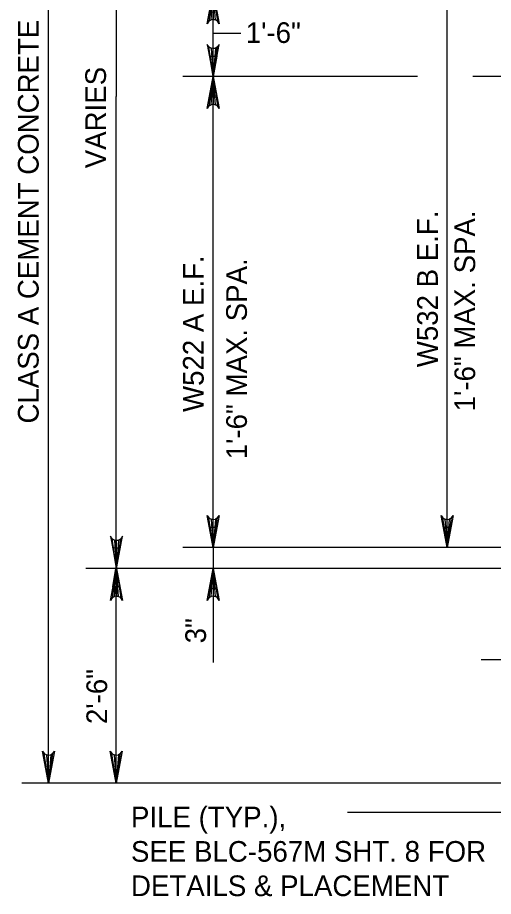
# Model space of a CAD drawing. Extents: x 638340 to 640242, y 295465 to 298435.
# Drawn here: x 639000.8 to 639069.8, y 295804.4 to 295932 of the extents above; entities that cross this region are included whole.
import ezdxf

# ---------------------------------------------------------------- set-up
doc = ezdxf.new("R2010")
doc.units = 0
doc.layers.add('Level 3', color=7, linetype='Continuous')
doc.layers.add('Level 4', color=7, linetype='Continuous')

msp = doc.modelspace()

# ---------------------------------------------------------------- linework, layer by layer
at = {"layer": 'Level 3'}
for p, q in [((639029.13, 295929.71), (639033.15, 295929.71)), ((639105.85, 295816.54), (639048.6, 295816.54))]:
    msp.add_line(p, q, dxfattribs=at)
at = {"layer": 'Level 4'}
for p, q in [((639005.25, 295820.81), (639005.25, 295989.02)), ((639015.06, 295989.02), (639015.06, 295920.5)), ((639063.04, 295855.02), (639063.04, 295937.09)), ((639029.13, 295926.36), (639029.13, 295932.78)), ((639028.55, 295923.41), (639024.71, 295923.41)), ((639058.77, 295923.41), (639024.71, 295923.41)), ((639029.13, 295855.02), (639029.13, 295923.41)), ((639124.35, 295923.41), (639066.79, 295923.41)), ((639015.06, 295854.94), (639015.06, 295920.5)), ((639085.93, 295855.02), (639024.71, 295855.02)), ((639029.13, 295855.02), (639029.13, 295838.31)), ((639083.79, 295855.02), (639053.64, 295855.02)), ((639094.01, 295851.99), (639010.64, 295851.99)), ((639094.01, 295851.99), (639024.01, 295851.99)), ((639060.4, 295851.99), (639024.71, 295851.99)), ((639015.06, 295820.81), (639015.06, 295849.31)), ((639029.13, 295849.04), (639029.13, 295846.1)), ((639097.46, 295838.69), (639067.96, 295838.69)), ((639094.01, 295820.81), (639001.39, 295820.81))]:
    msp.add_line(p, q, dxfattribs=at)
for points in [[(639029.13, 295935.72), (639030, 295931.07), (639029.76, 295931.43), (639029.45, 295931.62), (639029.13, 295931.67), (639028.82, 295931.62), (639028.51, 295931.43), (639028.26, 295931.07), (639029.13, 295935.72), (639028.51, 295931.43), (639028.82, 295931.62), (639029.13, 295935.72), (639029.13, 295931.67), (639029.45, 295931.62), (639029.13, 295935.72), (639029.76, 295931.43)], [(639029.13, 295923.41), (639030, 295928.06), (639029.76, 295927.71), (639029.45, 295927.52), (639029.13, 295927.47), (639028.82, 295927.52), (639028.51, 295927.71), (639028.26, 295928.06), (639029.13, 295923.41), (639028.51, 295927.71), (639028.82, 295927.52), (639029.13, 295923.41), (639029.13, 295927.47), (639029.45, 295927.52), (639029.13, 295923.41), (639029.76, 295927.71)], [(639029.13, 295923.41), (639030, 295918.76), (639029.76, 295919.12), (639029.45, 295919.3), (639029.13, 295919.36), (639028.82, 295919.3), (639028.51, 295919.12), (639028.26, 295918.76), (639029.13, 295923.41), (639028.51, 295919.12), (639028.82, 295919.3), (639029.13, 295923.41), (639029.13, 295919.36), (639029.45, 295919.3), (639029.13, 295923.41), (639029.76, 295919.12)], [(639029.13, 295855.02), (639028.26, 295859.67), (639028.51, 295859.31), (639028.82, 295859.13), (639029.13, 295859.07), (639029.45, 295859.13), (639029.76, 295859.31), (639030, 295859.67), (639029.13, 295855.02), (639029.76, 295859.31), (639029.45, 295859.13), (639029.13, 295855.02), (639029.13, 295859.07), (639028.82, 295859.13), (639029.13, 295855.02), (639028.51, 295859.31)], [(639063.04, 295855.02), (639062.16, 295859.67), (639062.41, 295859.31), (639062.72, 295859.13), (639063.04, 295859.07), (639063.35, 295859.13), (639063.66, 295859.31), (639063.91, 295859.67), (639063.04, 295855.02), (639063.66, 295859.31), (639063.35, 295859.13), (639063.04, 295855.02), (639063.04, 295859.07), (639062.72, 295859.13), (639063.04, 295855.02), (639062.41, 295859.31)], [(639015.1, 295851.99), (639015.97, 295856.64), (639015.72, 295856.28), (639015.41, 295856.1), (639015.1, 295856.04), (639014.79, 295856.1), (639014.48, 295856.28), (639014.23, 295856.64), (639015.1, 295851.99), (639014.48, 295856.28), (639014.79, 295856.1), (639015.1, 295851.99), (639015.1, 295856.04), (639015.41, 295856.1), (639015.1, 295851.99), (639015.72, 295856.28)], [(639015.1, 295851.99), (639015.97, 295847.34), (639015.72, 295847.7), (639015.41, 295847.88), (639015.1, 295847.94), (639014.79, 295847.88), (639014.48, 295847.7), (639014.23, 295847.34), (639015.1, 295851.99), (639014.48, 295847.7), (639014.79, 295847.88), (639015.1, 295851.99), (639015.1, 295847.94), (639015.41, 295847.88), (639015.1, 295851.99), (639015.72, 295847.7)], [(639029.13, 295851.99), (639030, 295847.34), (639029.76, 295847.7), (639029.45, 295847.88), (639029.13, 295847.94), (639028.82, 295847.88), (639028.51, 295847.7), (639028.26, 295847.34), (639029.13, 295851.99), (639028.51, 295847.7), (639028.82, 295847.88), (639029.13, 295851.99), (639029.13, 295847.94), (639029.45, 295847.88), (639029.13, 295851.99), (639029.76, 295847.7)], [(639005.25, 295820.81), (639004.38, 295825.46), (639004.63, 295825.11), (639004.94, 295824.92), (639005.25, 295824.87), (639005.56, 295824.92), (639005.88, 295825.11), (639006.12, 295825.46), (639005.25, 295820.81), (639005.88, 295825.11), (639005.56, 295824.92), (639005.25, 295820.81), (639005.25, 295824.87), (639004.94, 295824.92), (639005.25, 295820.81), (639004.63, 295825.11)], [(639015.06, 295820.81), (639014.18, 295825.46), (639014.43, 295825.11), (639014.74, 295824.92), (639015.06, 295824.87), (639015.37, 295824.92), (639015.68, 295825.11), (639015.93, 295825.46), (639015.06, 295820.81), (639015.68, 295825.11), (639015.37, 295824.92), (639015.06, 295820.81), (639015.06, 295824.87), (639014.74, 295824.92), (639015.06, 295820.81), (639014.43, 295825.11)]]:
    msp.add_lwpolyline(points, dxfattribs=at)
for points in [[(639028.64, 295926.36), (639029.63, 295926.36), (639029.13, 295923.41)], [(639028.64, 295920.47), (639029.63, 295920.47), (639029.13, 295923.41)], [(639028.64, 295857.96), (639029.63, 295857.96), (639029.13, 295855.02)], [(639062.54, 295857.96), (639063.53, 295857.96), (639063.04, 295855.02)], [(639015.55, 295854.94), (639014.57, 295854.94), (639015.06, 295851.99)], [(639015.55, 295849.31), (639014.57, 295849.31), (639015.06, 295852.25)], [(639028.64, 295849.04), (639029.63, 295849.04), (639029.13, 295851.99)]]:
    msp.add_lwpolyline(points, close=True, dxfattribs=at)

# ---------------------------------------------------------------- texts
at = {"layer": 'Level 3'}
for s, p in [('3"', (639028.08, 295841.1)), ('2\'-6"', (639013.74, 295829.38))]:
    msp.add_text(s, height=3, rotation=90, dxfattribs=at).set_placement(p)
for s, p in [('PILE (TYP.), ', (639017.2, 295814.39)), ('SEE BLC-567M SHT. 8 FOR', (639017.2, 295809.39)), ('DETAILS & PLACEMENT  ', (639017.2, 295804.4))]:
    msp.add_text(s, height=3.0001, dxfattribs=at).set_placement(p)
at = {"layer": 'Level 4'}
for s, height, p in [('CLASS A CEMENT CONCRETE', 3.0001, (639003.81, 295873.02)), ('VARIES', 3, (639013.58, 295910.08)), ('W532 B E.F.', 3.0001, (639061.7, 295881.19)), ('1\'-6" MAX. SPA.', 3.0001, (639067.11, 295874.79)), ('W522 A E.F.', 3.0001, (639027.74, 295874.69)), ('1\'-6" MAX. SPA.', 3.0001, (639034.01, 295867.83))]:
    msp.add_text(s, height=height, rotation=90, dxfattribs=at).set_placement(p)
msp.add_text('1\'-6"', height=3, dxfattribs=at).set_placement((639033.85, 295928.27))

doc.saveas('drawing.dxf')
